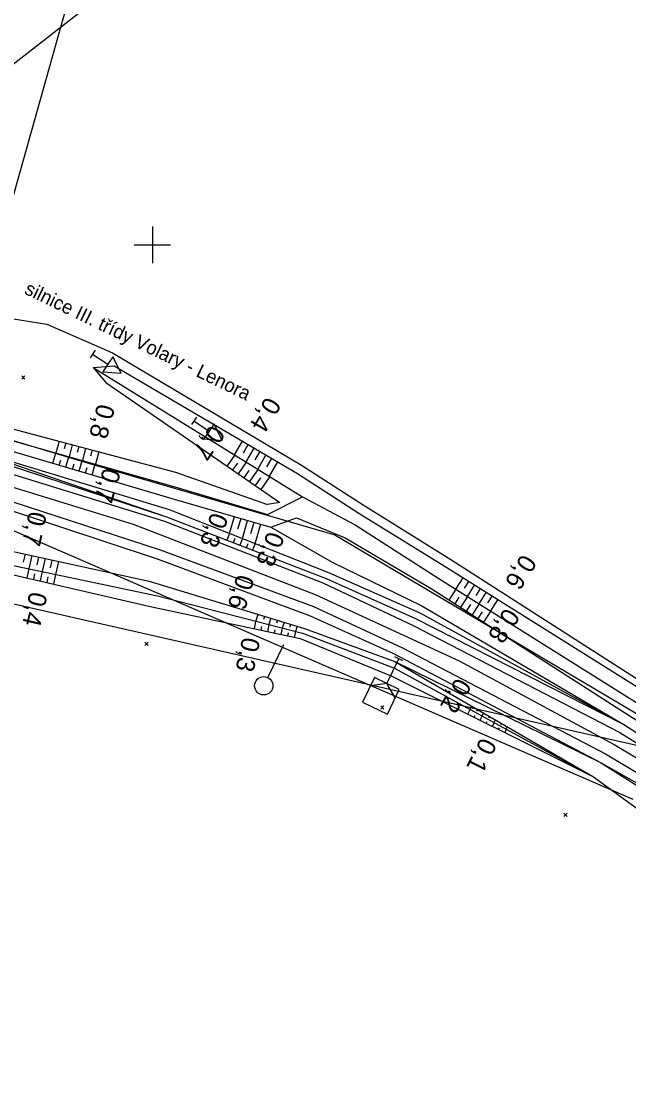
# Model space of a CAD drawing. Extents: x -804899 to -803847, y -1165742 to -1164942.
# Drawn here: x -804714.3 to -804647.9, y -1165193.1 to -1165075.5 of the extents above; entities that cross this region are included whole.
import ezdxf

# ---------------------------------------------------------------- set-up
doc = ezdxf.new("R2010")
doc.units = 0
for name, color, linetype in [('0381KM061-064P - Vrstva 1', 7, 'Continuous'), ('0381KM061-064P - Vrstva 36', 7, 'Continuous'), ('0381KM061-064P - Vrstva 4', 7, 'Continuous'), ('0381KM061-064P - Vrstva 48', 7, 'Continuous'), ('0381KM061-064P - Vrstva 49', 7, 'Continuous'), ('0381KM061-064P - Vrstva 51', 7, 'Continuous'), ('0381KM061-064P - Vrstva 55', 7, 'Continuous'), ('0381KM061-064P - Vrstva 7', 7, 'Continuous'), ('0381KM061-064P - Vrstva 8', 7, 'Continuous'), ('hran DP - hran DP', 7, 'Continuous'), ('krizky_1000 - Vrstva 1', 7, 'Continuous'), ('vyt_sit - polygon', 7, 'Continuous')]:
    doc.layers.add(name, color=color, linetype=linetype)

msp = doc.modelspace()

# ---------------------------------------------------------------- linework, layer by layer
at = {"layer": '0381KM061-064P - Vrstva 1'}
for points in [[(-804748.02, -1165118.72), (-804737.69, -1165120.7), (-804722.06, -1165124.43), (-804702.11, -1165130.56), (-804682.19, -1165138.24), (-804666.44, -1165145.5)], [(-804666.44, -1165145.5), (-804649.48, -1165154.65), (-804645.14, -1165157.27), (-804633.7, -1165164.38), (-804619.36, -1165173.74)]]:
    msp.add_lwpolyline(points, dxfattribs=at)
at = {"layer": '0381KM061-064P - Vrstva 36'}
for p, q in [((-804687.37, -1165147.34), (-804685.62, -1165143.74)), ((-804687.81, -1165148.24), (-804687.81, -1165148.24))]:
    msp.add_line(p, q, dxfattribs=at)
msp.add_circle((-804687.81, -1165148.24), 1, dxfattribs=at)
at = {"layer": '0381KM061-064P - Vrstva 4'}
for points in [[(-804755.73, -1165115.93), (-804748.17, -1165116.91), (-804721.25, -1165123.25), (-804698.66, -1165130.22), (-804681.33, -1165136.99), (-804671.47, -1165141.65), (-804648.84, -1165153.36), (-804638.11, -1165160.03), (-804624.48, -1165168.7), (-804602.56, -1165183.07), (-804574.47, -1165201.72), (-804542.72, -1165222.84), (-804507.36, -1165246.55), (-804477.08, -1165266.82), (-804448.75, -1165285.88), (-804421.18, -1165304.15), (-804392.89, -1165323.09), (-804369.85, -1165338.37), (-804348.86, -1165352.04), (-804325.13, -1165367.98), (-804299.32, -1165385.27), (-804266.05, -1165407.31), (-804234.28, -1165428.6)], [(-804755.73, -1165115.93), (-804748.03, -1165116.49), (-804721.05, -1165122.36), (-804698.44, -1165129.77), (-804680.98, -1165136.5), (-804671.21, -1165140.89), (-804648.42, -1165152.46), (-804637.55, -1165159.43), (-804624.04, -1165168.29), (-804602.25, -1165182.38), (-804573.74, -1165201.2), (-804542.46, -1165222.56), (-804507.06, -1165246.03), (-804476.47, -1165266.24), (-804448.31, -1165285.08), (-804421.02, -1165303.1), (-804392.59, -1165322.59), (-804369.41, -1165337.65), (-804348.68, -1165351.59), (-804324.76, -1165367.42), (-804298.9, -1165384.42), (-804265.65, -1165406.5), (-804234.05, -1165428.04)], [(-804760.26, -1165118.8), (-804748.36, -1165120.01), (-804721.79, -1165126), (-804699.13, -1165133.38), (-804682.38, -1165139.58), (-804672.62, -1165144.09), (-804650.43, -1165155.7), (-804639.38, -1165162.29), (-804626.13, -1165170.89), (-804604.37, -1165185.52), (-804576.36, -1165204.15)], [(-804760.26, -1165118.8), (-804748.39, -1165120.75), (-804721.77, -1165126.98), (-804699.38, -1165134.38), (-804682.72, -1165140.57), (-804673.68, -1165144.67), (-804650.96, -1165156.64), (-804639.65, -1165163.02), (-804626.64, -1165171.43)]]:
    msp.add_lwpolyline(points, dxfattribs=at)
at = {"layer": '0381KM061-064P - Vrstva 48'}
for p, q in [((-804710.21, -1165121.48), (-804710.55, -1165122.77)), ((-804709.48, -1165121.67), (-804709.66, -1165122.33)), ((-804708.76, -1165121.87), (-804709.11, -1165123.18)), ((-804708.03, -1165122.06), (-804708.21, -1165122.72)), ((-804707.31, -1165122.25), (-804707.66, -1165123.59)), ((-804691.03, -1165122.96), (-804690.15, -1165121.47)), ((-804690.04, -1165122.75), (-804689.51, -1165121.85)), ((-804689.75, -1165123.74), (-804688.86, -1165122.23)), ((-804710.9, -1165123.89), (-804710.57, -1165122.77)), ((-804710.18, -1165124.1), (-804710.01, -1165123.54)), ((-804709.46, -1165124.31), (-804709.13, -1165123.18)), ((-804708.02, -1165124.74), (-804707.68, -1165123.59)), ((-804706.58, -1165122.44), (-804706.76, -1165123.12)), ((-804705.86, -1165122.63), (-804706.22, -1165124)), ((-804690.99, -1165122.98), (-804691.83, -1165124.19)), ((-804688.75, -1165123.53), (-804688.21, -1165122.61)), ((-804688.47, -1165124.53), (-804687.57, -1165122.99)), ((-804687.47, -1165124.3), (-804686.92, -1165123.37)), ((-804708.74, -1165124.53), (-804708.57, -1165123.96)), ((-804707.31, -1165124.95), (-804707.13, -1165124.37)), ((-804706.59, -1165125.17), (-804706.24, -1165124)), ((-804690.7, -1165123.87), (-804691.22, -1165124.62)), ((-804689.72, -1165123.76), (-804690.6, -1165125.04)), ((-804689.44, -1165124.68), (-804689.98, -1165125.47)), ((-804688.44, -1165124.55), (-804689.36, -1165125.9)), ((-804687.2, -1165125.32), (-804686.28, -1165123.75)), ((-804688.18, -1165125.5), (-804688.75, -1165126.32)), ((-804687.16, -1165125.34), (-804688.13, -1165126.75)), ((-804691.55, -1165131.57), (-804691.02, -1165129.73)), ((-804690.63, -1165131.08), (-804690.3, -1165129.93)), ((-804690.15, -1165132.12), (-804689.58, -1165130.14)), ((-804689.21, -1165131.58), (-804688.85, -1165130.35)), ((-804688.74, -1165132.67), (-804688.14, -1165130.56)), ((-804691.55, -1165131.57), (-804691.84, -1165132.32)), ((-804690.97, -1165132.14), (-804691.14, -1165132.59)), ((-804690.15, -1165132.12), (-804690.44, -1165132.86)), ((-804689.57, -1165132.69), (-804689.74, -1165133.13)), ((-804688.76, -1165132.67), (-804689.04, -1165133.4)), ((-804714.08, -1165134.71), (-804713.89, -1165133.84)), ((-804713.48, -1165135.44), (-804713.16, -1165134)), ((-804712.62, -1165135.02), (-804712.43, -1165134.16)), ((-804712.01, -1165135.75), (-804711.7, -1165134.32)), ((-804711.15, -1165135.34), (-804710.97, -1165134.48)), ((-804710.55, -1165136.06), (-804710.23, -1165134.64)), ((-804713.52, -1165135.43), (-804713.75, -1165136.43)), ((-804712.88, -1165136), (-804713.02, -1165136.6)), ((-804712.05, -1165135.74), (-804712.29, -1165136.77)), ((-804711.42, -1165136.32), (-804711.56, -1165136.94)), ((-804710.59, -1165136.05), (-804710.83, -1165137.11)), ((-804666.78, -1165137.66), (-804666.01, -1165136.43)), ((-804666.78, -1165137.66), (-804667.55, -1165138.86)), ((-804665.84, -1165137.57), (-804665.37, -1165136.83)), ((-804665.51, -1165138.46), (-804664.74, -1165137.23)), ((-804664.57, -1165138.36), (-804664.1, -1165137.62)), ((-804666.45, -1165138.54), (-804666.91, -1165139.26)), ((-804665.51, -1165138.46), (-804666.28, -1165139.67)), ((-804664.24, -1165139.26), (-804663.47, -1165138.02)), ((-804663.3, -1165139.16), (-804662.83, -1165138.42)), ((-804662.97, -1165140.05), (-804662.2, -1165138.82)), ((-804665.18, -1165139.34), (-804665.65, -1165140.07)), ((-804664.24, -1165139.26), (-804665.02, -1165140.48)), ((-804662.97, -1165140.05), (-804663.76, -1165141.29)), ((-804688.84, -1165142.01), (-804688.66, -1165141.19)), ((-804688.46, -1165140.41), (-804688.69, -1165141.18)), ((-804687.74, -1165140.63), (-804687.85, -1165141)), ((-804687.02, -1165140.85), (-804687.24, -1165141.55)), ((-804686.31, -1165141.06), (-804686.41, -1165141.4)), ((-804663.92, -1165140.15), (-804664.39, -1165140.88)), ((-804688.1, -1165142.16), (-804688.02, -1165141.77)), ((-804687.37, -1165142.32), (-804687.21, -1165141.56)), ((-804686.64, -1165142.48), (-804686.56, -1165142.11)), ((-804685.9, -1165142.63), (-804685.76, -1165141.94)), ((-804685.59, -1165141.28), (-804685.78, -1165141.93)), ((-804684.87, -1165141.5), (-804684.96, -1165141.81)), ((-804684.44, -1165142.95), (-804684.3, -1165142.31)), ((-804684.15, -1165141.72), (-804684.33, -1165142.31)), ((-804685.17, -1165142.79), (-804685.1, -1165142.46)), ((-804665.07, -1165150.48), (-804665.27, -1165150.82)), ((-804665.47, -1165151.34), (-804665.22, -1165150.85)), ((-804664.8, -1165151.68), (-804664.68, -1165151.44)), ((-804664.42, -1165150.85), (-804664.52, -1165151.02)), ((-804664.13, -1165152.01), (-804663.91, -1165151.57)), ((-804663.77, -1165151.23), (-804663.96, -1165151.54)), ((-804663.13, -1165151.61), (-804663.21, -1165151.75)), ((-804663.46, -1165152.35), (-804663.35, -1165152.14)), ((-804662.79, -1165152.68), (-804662.59, -1165152.29)), ((-804662.48, -1165151.98), (-804662.64, -1165152.26)), ((-804662.12, -1165153.02), (-804662.02, -1165152.83)), ((-804661.83, -1165152.36), (-804661.9, -1165152.49)), ((-804661.18, -1165152.74), (-804661.32, -1165152.98)), ((-804661.45, -1165153.35), (-804661.27, -1165153.01))]:
    msp.add_line(p, q, dxfattribs=at)
at = {"layer": '0381KM061-064P - Vrstva 49'}
for p, q in [((-804713.94, -1165114.69), (-804714.29, -1165114.34)), ((-804713.94, -1165114.34), (-804714.29, -1165114.69)), ((-804700.46, -1165143.82), (-804700.81, -1165143.47)), ((-804700.46, -1165143.47), (-804700.81, -1165143.82)), ((-804673.48, -1165145.6), (-804650.96, -1165156.64)), ((-804674.66, -1165150.8), (-804675.01, -1165150.45)), ((-804674.66, -1165150.45), (-804675.01, -1165150.8)), ((-804654.61, -1165162.53), (-804654.97, -1165162.18)), ((-804654.61, -1165162.18), (-804654.97, -1165162.53))]:
    msp.add_line(p, q, dxfattribs=at)
for points in [[(-804755.73, -1165115.93), (-804751.24, -1165112.25), (-804747.15, -1165112.99), (-804720.56, -1165118.75), (-804697.46, -1165124.86)], [(-804706.48, -1165113.41), (-804704.19, -1165113.22), (-804684.11, -1165125.02), (-804677.29, -1165129.42), (-804668.09, -1165135.13)], [(-804706.48, -1165113.41), (-804683.56, -1165127.57)], [(-804706.48, -1165113.41), (-804705.1, -1165115.06), (-804686.07, -1165128.17), (-804687.41, -1165128.4)], [(-804754.42, -1165115.02), (-804748.04, -1165114.39), (-804721.19, -1165119.75), (-804697.28, -1165126.54)], [(-804755.73, -1165115.93), (-804747.85, -1165115.39), (-804738.73, -1165116.75), (-804720.93, -1165120.92), (-804697.63, -1165127.82)], [(-804738.73, -1165116.75), (-804737.5, -1165118.13), (-804721.08, -1165121.98), (-804698.17, -1165128.96), (-804680.73, -1165135.83), (-804670.75, -1165140.27), (-804648.42, -1165152.46)], [(-804721.08, -1165121.98), (-804698.44, -1165129.77), (-804680.98, -1165136.5), (-804671.21, -1165140.89), (-804648.42, -1165152.46)], [(-804766.83, -1165123.91), (-804764.89, -1165122.96), (-804750.44, -1165127.42), (-804724.29, -1165131.56), (-804700.35, -1165136.81), (-804683.35, -1165141.96), (-804673.48, -1165145.6), (-804651.73, -1165158.22)], [(-804766.32, -1165124.35), (-804750.31, -1165128.3), (-804724.8, -1165133.06), (-804699.44, -1165138.4), (-804683.58, -1165142.5), (-804673.52, -1165146.32), (-804651.73, -1165158.22)], [(-804697.46, -1165124.86), (-804687.41, -1165128.4)], [(-804697.28, -1165126.54), (-804687.39, -1165129.5), (-804683.56, -1165127.57)], [(-804697.63, -1165127.82), (-804687.02, -1165130.88), (-804684.24, -1165129.87), (-804678.91, -1165132.05), (-804669.51, -1165137.6)], [(-804683.56, -1165127.57), (-804677.8, -1165130.64), (-804668.53, -1165136.56)], [(-804687.02, -1165130.88), (-804680.25, -1165134.76), (-804670.53, -1165139.48)], [(-804724.99, -1165133.83), (-804700.39, -1165139.54), (-804683.82, -1165143.08), (-804673.79, -1165147.18), (-804651.73, -1165158.22)], [(-804668.09, -1165135.13), (-804646.08, -1165148.91), (-804635.34, -1165155.79), (-804621.98, -1165164.4), (-804599.68, -1165178.86), (-804570.23, -1165197.63), (-804539.04, -1165217.4), (-804503.79, -1165239.32), (-804473.21, -1165259.25), (-804445.02, -1165277.37), (-804416.3, -1165295.6), (-804385.23, -1165314.87), (-804342.84, -1165342.16), (-804322.16, -1165355.5), (-804292.15, -1165374.6), (-804262.58, -1165393.44), (-804234.25, -1165411.43)], [(-804669.51, -1165137.6), (-804647.83, -1165151.5), (-804636.87, -1165158.28), (-804626.96, -1165165.56)], [(-804668.53, -1165136.56), (-804646.51, -1165150.38), (-804635.75, -1165157.19), (-804622.88, -1165165.28), (-804600.74, -1165180), (-804571.06, -1165199.05), (-804539.91, -1165219.23), (-804504.85, -1165241.38), (-804474.07, -1165260.59), (-804445.75, -1165278.86), (-804417.38, -1165297.08), (-804386.13, -1165316.29), (-804343.68, -1165343.22), (-804323.05, -1165356.81), (-804293.41, -1165375.48), (-804263.45, -1165394.43), (-804234.68, -1165412.78)], [(-804670.53, -1165139.48), (-804648.42, -1165152.46)], [(-804650.96, -1165156.64), (-804629.95, -1165169.87)], [(-804651.73, -1165158.22), (-804641.24, -1165165.82), (-804629.21, -1165174.28), (-804606.38, -1165188.59), (-804578.69, -1165207.38), (-804546.55, -1165228.41), (-804509.4, -1165252.77), (-804482.02, -1165272.35), (-804454.07, -1165289.87), (-804424.02, -1165310.32)]]:
    msp.add_lwpolyline(points, dxfattribs=at)
at = {"layer": '0381KM061-064P - Vrstva 51'}
for p, q in [((-804706.26, -1165111.53), (-804706.82, -1165112.36)), ((-804695.16, -1165118.83), (-804695.73, -1165119.65))]:
    msp.add_line(p, q, dxfattribs=at)
for points in [[(-804728.9, -1165105.9), (-804711.54, -1165108.67), (-804704.35, -1165111.8), (-804683.69, -1165124.09), (-804676.95, -1165128.43), (-804667.36, -1165134.41), (-804645.71, -1165148.3), (-804634.7, -1165155.23), (-804621.63, -1165163.62), (-804599.19, -1165178.23), (-804569.67, -1165197.16), (-804538.42, -1165216.77), (-804503.41, -1165238.94), (-804472.82, -1165258.55), (-804444.57, -1165276.4), (-804415.82, -1165294.73), (-804384.7, -1165314.57), (-804342.59, -1165341.72), (-804321.8, -1165355.02), (-804291.77, -1165374.22), (-804262.45, -1165392.96)], [(-804706.54, -1165111.95), (-804704.88, -1165113.06), (-804705.43, -1165113.89), (-804703.42, -1165114.03), (-804704.32, -1165112.23), (-804704.88, -1165113.06)], [(-804695.45, -1165119.24), (-804693.8, -1165120.39), (-804694.38, -1165121.21), (-804692.37, -1165121.39), (-804693.23, -1165119.57), (-804693.8, -1165120.39)]]:
    msp.add_lwpolyline(points, dxfattribs=at)
at = {"layer": '0381KM061-064P - Vrstva 55'}
msp.add_lwpolyline([(-804834.02, -1165173.21), (-804777.95, -1165165.95), (-804761.65, -1165133.49), (-804755.48, -1165121.19), (-804751.26, -1165114.04), (-804741.92, -1165100.8), (-804736.13, -1165096.49), (-804701.79, -1165069.72), (-804628.3, -1165012.44)], dxfattribs=at)
at = {"layer": '0381KM061-064P - Vrstva 7'}
for p, q in [((-804674.33, -1165147.99), (-804673.03, -1165145.29)), ((-804672.58, -1165145.51), (-804673.48, -1165145.07))]:
    msp.add_line(p, q, dxfattribs=at)
for points in [[(-804674.33, -1165147.99), (-804675.68, -1165147.34), (-804676.99, -1165150.04), (-804674.28, -1165151.35), (-804672.98, -1165148.64), (-804674.33, -1165147.99)], [(-804673.42, -1165149.55), (-804674.33, -1165147.99), (-804676.12, -1165148.24)]]:
    msp.add_lwpolyline(points, dxfattribs=at)
at = {"layer": '0381KM061-064P - Vrstva 8'}
msp.add_line((-804722.5, -1165120.54), (-804702.47, -1165049.27), dxfattribs=at)
at = {"layer": 'hran DP - hran DP'}
for p, q in [((-804735.44, -1165115.31), (-804706.98, -1165123.89)), ((-804706.98, -1165123.89), (-804680.02, -1165131.72)), ((-804647.39, -1165160.7), (-804728.07, -1165125.68)), ((-804680.02, -1165131.72), (-804619.47, -1165167.61))]:
    msp.add_line(p, q, dxfattribs=at)
at = {"layer": 'krizky_1000 - Vrstva 1'}
for points in [[(-804700, -1165098), (-804700, -1165102)], [(-804702, -1165100), (-804698, -1165100)]]:
    msp.add_lwpolyline(points, dxfattribs=at)
at = {"layer": 'vyt_sit - polygon'}
msp.add_line((-804641.93, -1165155.93), (-804836.52, -1165111.83), dxfattribs=at)

# ---------------------------------------------------------------- texts
at = {"layer": '0381KM061-064P - Vrstva 48'}
for s, rotation, p in [('0,8', 255.1809, (-804705.99, -1165117.28)), ('0,4', 239.5582, (-804687.53, -1165116.49)), ('0,7', 235.4402, (-804693.57, -1165119.56)), ('0,7', 253.4991, (-804705.33, -1165124.27)), ('0,7', 257.6347, (-804713.48, -1165129.05)), ('0,3', 248.475, (-804693.49, -1165129.14)), ('0,3', 248.9077, (-804687.35, -1165131.22)), ('0,6', 237.9371, (-804659.53, -1165133.71)), ('0,6', 253.1416, (-804690.71, -1165135.94)), ('0,4', 256.9301, (-804713.4, -1165137.84)), ('0,8', 237.3341, (-804661.36, -1165139.59)), ('0,3', 257.9404, (-804690.13, -1165142.82)), ('0,2', 239.8871, (-804666.72, -1165147.24)), ('0,1', 243.4194, (-804664.02, -1165153.78))]:
    msp.add_text(s, height=2, rotation=rotation, dxfattribs=at).set_placement(p)
at = {"layer": '0381KM061-064P - Vrstva 51'}
msp.add_text('silnice III. třídy Volary - Lenora', height=1.5, rotation=334.2578, dxfattribs=at).set_placement((-804714.1, -1165105.29))

doc.saveas('drawing.dxf')
